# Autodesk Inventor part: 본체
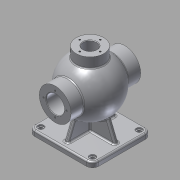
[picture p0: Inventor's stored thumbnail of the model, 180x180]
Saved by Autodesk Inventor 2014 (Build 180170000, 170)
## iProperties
Created: 2015-10
Part Number: 본체
Material: Aluminum 6061
Document SubType Name: Modeling
Designer: youjin04
Density: 2.71 g/cm^3
Appearance: Aluminum - Flat
Mass: 1509.57 g
Surface Area: 1153.7 cm^2
Volume: 557.037 cm^3
Author: youjin04
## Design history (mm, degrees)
sketch "Sketch1"
  geometry: L1 (-62.5, 57.5)-(62.5, 57.5); L2 (62.5, 57.5)-(62.5, -57.5); L3 (62.5, -57.5)-(-62.5, -57.5); L4 (-62.5, -57.5)-(-62.5, 57.5); L5 (-62.5, 57.5)-(62.5, -57.5); L6 (62.5, 57.5)-(-62.5, -57.5); 3 further points
  constraints: 12 end point, 3 midpoint, 2 parallel, 1 coincident, 1 horizontal, 1 perpendicular
  dimensions: "d0" = 125 distance of L2.end L3.end; "d1" = 115 distance of L1.end L2.end
extrude "Extrusion1" new body sketch "Sketch1" distance "d2" = 10; taper "d3" = 0 deg
fillet "Fillet1" dims "d4" = 12
sketch "Sketch2" dims "d5" = 53
  geometry: L1 (40.677, 118.976)-(-40.677, 51.024); A1 r 53 centre (0, 85) between (40.677, 118.976) and (-40.677, 51.024); 2 further points
  constraints: 2 end point, 2 point on circle, 1 centre point, 1 coincident, 1 midpoint, 1 vertical alignment, 4 other
  dimensions: "d6" = 85 distance of point (0, 0) point (0, 85)
revolve "Revolution1" sketch "Sketch2" stored, may be unused: angle "d7" = 90 deg
sketch "Sketch3"
  geometry: C1 r 31 at (0, 85); 1 further point
  constraints: 1 centre point, 1 vertical alignment
  dimensions: "d8" = 62 diameter of C1; "d9" = 85 distance of point (0, 0) C1.centre
extrude "Extrusion2" join sketch "Sketch3" stored distance "d10" = 136; taper "d11" = 0 deg
workplane "Work Plane1"
sketch "Sketch4"
  geometry: C1 r 27 at (0, 0); 1 further point
  constraints: 1 centre point, 1 coincident
  dimensions: "d13" = 54 diameter of C1
extrude "Extrusion3" join sketch "Sketch4" stored distance "d14" = 136; taper "d15" = 0 deg
sketch "Sketch5" dims "d16" = 43
  geometry: L1 (37.568, 105.92)-(-37.568, 64.08); A1 r 43 centre (0, 85) between (37.568, 105.92) and (-37.568, 64.08); 2 further points
  constraints: 2 end point, 2 point on circle, 1 centre point, 1 coincident, 1 midpoint, 1 vertical alignment, 4 other
  dimensions: "d17" = 85 distance of point (0, 0) point (0, 85)
revolve "Revolution2" sketch "Sketch5" stored, may be unused: angle "d18" = 90 deg
sketch "Sketch6"
  geometry: C1 r 31 at (0, 0) reference; C2 r 17.5 at (0, 0); 1 further point
  constraints: 1 centre point, 1 coincident
  dimensions: "d19" = 35 diameter of C2
extrude "Extrusion4" cut sketch "Sketch6" stored distance "d20" = 136; taper "d21" = 0 deg
sketch "Sketch7"
  geometry: C1 r 27 at (0, 0) reference; C2 r 13 at (0, 0)
  constraints: 1 centre point, 1 coincident
  dimensions: "d22" = 26 diameter of C2
extrude "Extrusion5" cut sketch "Sketch7" stored distance "d23" = 0; taper "d24" = 0 deg
workplane "Work Plane2"
sketch "Sketch8"
  geometry: L1 (50.5, 85)-(-50.5, 85) reference; C1 r 18.5 at (0, 0); 1 further point
  constraints: 1 centre point, 1 vertical alignment
  dimensions: "d26" = 37 diameter of C1; "d27" = 85 distance from line of L1 C1.centre
extrude "Extrusion6" cut sketch "Sketch8" distance "d28" = 1.75; taper "d29" = 0 deg
workplane "Work Plane3"
sketch "Sketch11"
  geometry: L1 (-27, 150)-(27, 150) reference; L2 (-27, 150)-(-27, 130.607) reference; 2 further points
  constraints: 1 other
  dimensions: "d57" = 10 distance from line of L1 point (0, 140); "d58" = 27 distance from line of point (0, 140) L2
emboss "Emboss1" sketch "Sketch11" dims "d0" = 125, "d1" = 115, "d8" = 62, "d59" = 0.5, "d60" = 0
sketch "Sketch12"
  geometry: C1 r 17.5 at (0, 0) reference; C2 r 31 at (0, 0) reference; A1 r 22.5 centre (0, 0) between (0, 22.5) and (0, -22.5); 3 further points
  constraints: 4 point on circle, 2 horizontal alignment, 2 vertical alignment, 1 centre point, 1 coincident
  dimensions: "d61" = 45 diameter of A1
hole "Hole1" sketch "Sketch12" at (0, 22.5), (22.5, 0), (0, -22.5), (-22.5, 0) diameter "d62" = 3.242; stored, may be unused: countersink angle "d66" = 90 deg, drill point angle "d68" = 118 deg; dims "d63" = 12, "d64" = 4, "d65" = 2, "d67" = 15
sketch "Sketch13"
  geometry: C1 r 13 at (0, 0) reference; C2 r 27 at (0, 0) reference; A1 r 20 centre (0, 0) between (0, 20) and (20, 0); 2 further points
  constraints: 4 point on circle, 2 horizontal alignment, 2 vertical alignment, 1 centre point, 1 coincident
  dimensions: "d69" = 40 diameter of A1
hole "Hole2" sketch "Sketch13" at (0, 20), (20, 0), (0, -20), (-20, 0) diameter "d70" = 3.242; stored, may be unused: countersink angle "d74" = 90 deg, drill point angle "d76" = 118 deg; dims "d71" = 9, "d72" = 4, "d73" = 2, "d75" = 11
sketch "Sketch14"
  geometry: C1 r 17.5 at (0, 0) reference; C2 r 31 at (0, 0) reference; A1 r 24 centre (0, 0) between (0, 24) and (-24, 0); 3 further points
  constraints: 4 point on circle, 2 horizontal alignment, 2 vertical alignment, 1 centre point, 1 coincident
  dimensions: "d77" = 48 diameter of A1
hole "Hole3" sketch "Sketch14" at (0, 24), (24, 0), (0, -24), (-24, 0) diameter "d78" = 3.242; stored, may be unused: countersink angle "d82" = 90 deg, drill point angle "d84" = 118 deg; dims "d79" = 16, "d80" = 4, "d81" = 2, "d83" = 19
sketch "Sketch15"
  geometry: 5 further points
  dimensions: "d85" = 101 distance of point (-50.5, 45.5) point (50.5, 45.5); "d86" = 91 distance of point (50.5, -45.5) point (50.5, 45.5); "d87" = 50.5 horizontal distance of point (0, 0) point (50.5, 45.5); "d88" = 45.5 vertical distance of point (0, 0) point (50.5, -45.5); "d89" = 91 distance of point (-50.5, 45.5) point (-50.5, -45.5); "d90" = 45.5 vertical distance of point (0, 0) point (-50.5, -45.5); "d91" = 101 distance of point (-50.5, -45.5) point (50.5, -45.5); "d92" = 50.5 horizontal distance of point (0, 0) point (-50.5, -45.5)
hole "Hole4" sketch "Sketch15" at (-50.5, 45.5), (50.5, 45.5), (50.5, -45.5), (-50.5, -45.5) diameter "d93" = 8; stored, may be unused: countersink angle "d97" = 90 deg, drill point angle "d99" = 0 deg; dims "d94" = 16, "d95" = 12, "d96" = 3, "d98" = 10
fillet "Fillet2" dims "d100" = 3
sketch "Sketch16"
  geometry: L1 (-57.5, 0)-(-57.5, 10) reference; L2 (-68, 54)-(-44.497, 54) reference; L3 (44.497, 54)-(68, 54) reference; L4 (39.5, 10)-(51.5, 10) reference; L5 (45.5, 10)-(-45.5, 10) reference; L6 (45.5, 10)-(57.5, 10) reference; L7 (57.5, 10)-(57.5, 0) reference; L8 (-51.5, 10)-(-39.5, 10) reference; L9 (-57.5, 10)-(-45.5, 10) reference; L10 (31.202, 50.339)-(47.5, 10); L11 (-31.202, 50.339)-(-47.5, 10); A1 r 53 centre (0, 85) between (42.113, 117.179) and (42.113, 52.821) reference; A2 r 3 centre (-44.497, 51) between (-42.113, 52.821) and (-44.497, 54) reference; A3 r 3 centre (44.497, 51) between (44.497, 54) and (42.113, 52.821) reference; A4 r 46.637 centre (0, 85) between (-31.202, 50.339) and (31.202, 50.339); 1 further point
  constraints: 4 end point, 4 point on circle, 2 point on line, 1 centre point, 1 coincident
  dimensions: "d103" = 10 distance from line of L1 L11.end; "d105" = 10 distance of L6.end L10.end; "d107" = 22 deg angle of L10 L7; "d142" = 93.27323 diameter of A4; "d143" = 22 deg angle of L1 L11
chamfer "Chamfer1" distance "d137" = 1; stored, may be unused: second distance "d138" = 2, angle "d139" = 45 deg
fillet "Fillet9" dims "d140" = 3
feature "Rib7" dims "d144" = 1, "d145" = 8, "d146" = 0, "d147" = 0, "d148" = 1, "d149" = 1
sketch "Sketch18"
  geometry: L1 (-37.379, 47.426)-(-52.5, 10); L2 (37.379, 47.426)-(52.5, 10); L3 (-56.5, 10)-(-44.5, 10) reference; L4 (-50.5, 10)-(50.5, 10) reference; L5 (44.5, 10)-(56.5, 10) reference; L6 (-62.5, 0)-(-62.5, 7) reference; L7 (62.5, 7)-(62.5, 0) reference; A1 r 53 centre (0, 85) between (-28.393, 129.753) and (28.393, 129.753) reference; 1 further point
  constraints: 4 end point, 2 point on circle, 2 point on line
  dimensions: "d150" = 10 distance from line of L6 L1.end; "d151" = 22 deg angle of L6 L1; "d152" = 10 distance from line of L7 L2.end; "d153" = 22 deg angle of L7 L2
feature "Rib8" dims "d154" = 1, "d155" = 8, "d156" = 0, "d157" = 0, "d158" = 1, "d159" = 1
feature "Rib9" dims "d160" = 1, "d161" = 8, "d162" = 0, "d163" = 0, "d164" = 1, "d165" = 1
fillet "Fillet11" dims "d166" = 3
fillet "Fillet12" dims "d167" = 3
fillet "Fillet13" dims "d168" = 3
body "Solid1"
other parameters: "d25" = -16, "d56" = -27, "d104" = 22 deg, "d106" = 22 deg
